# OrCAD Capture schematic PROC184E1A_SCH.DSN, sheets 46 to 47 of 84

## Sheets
46 52. ON BOARD LIN: size C; title: LIN INTERFACE; note: PROC184_SCH
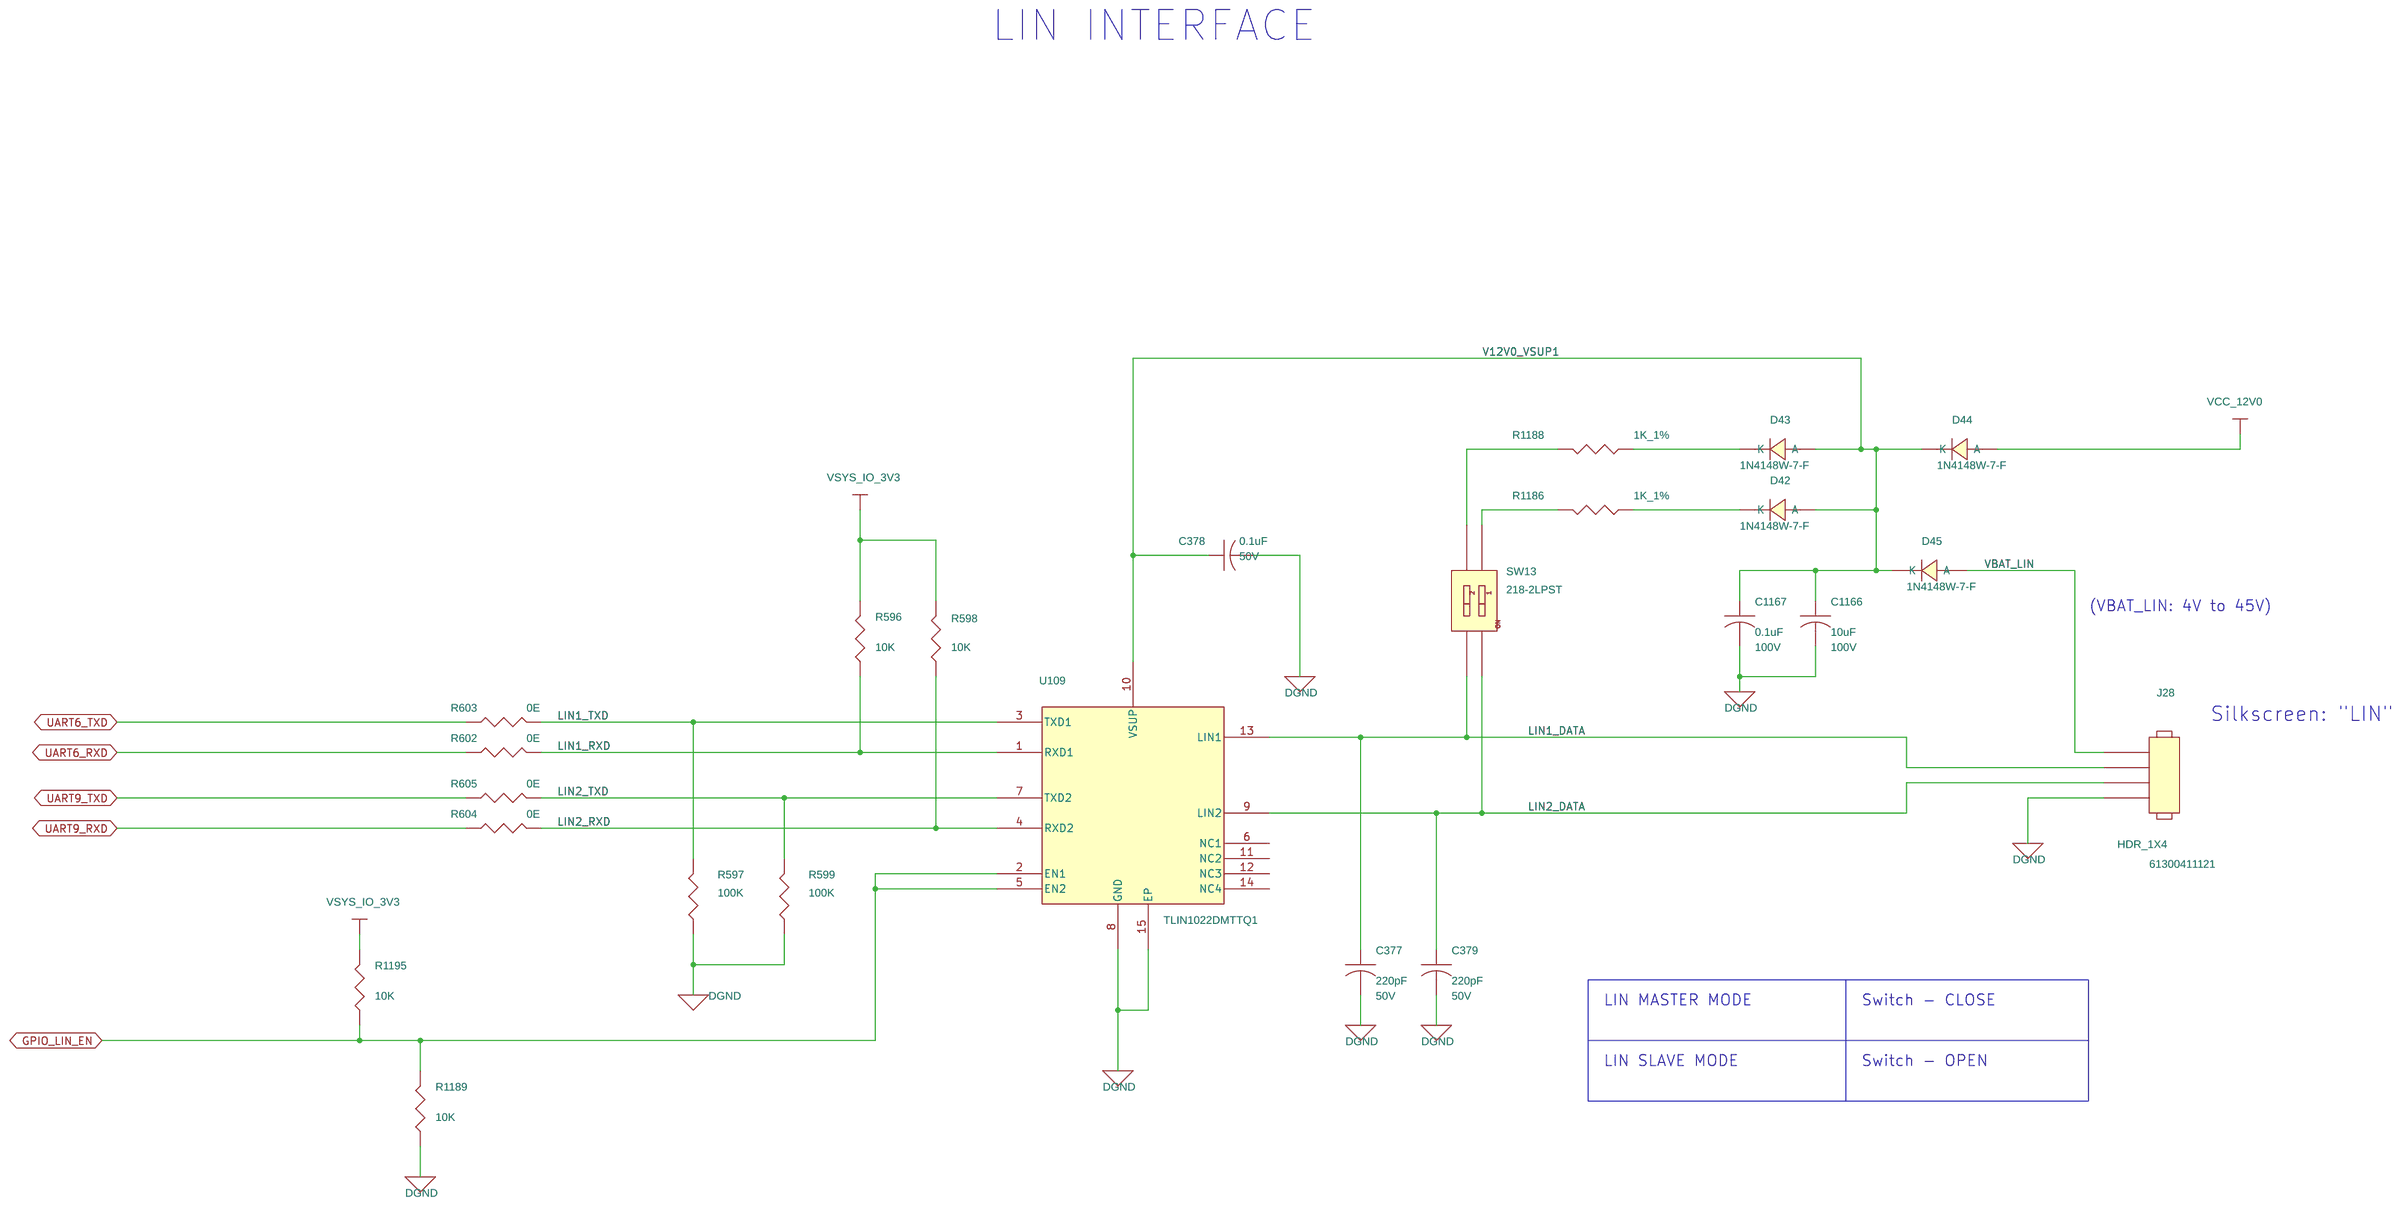
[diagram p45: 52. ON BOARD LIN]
47 50. XDS110 DEBUGGER: size C; title: XDS110 DEBUGGER; note: PROC184_SCH
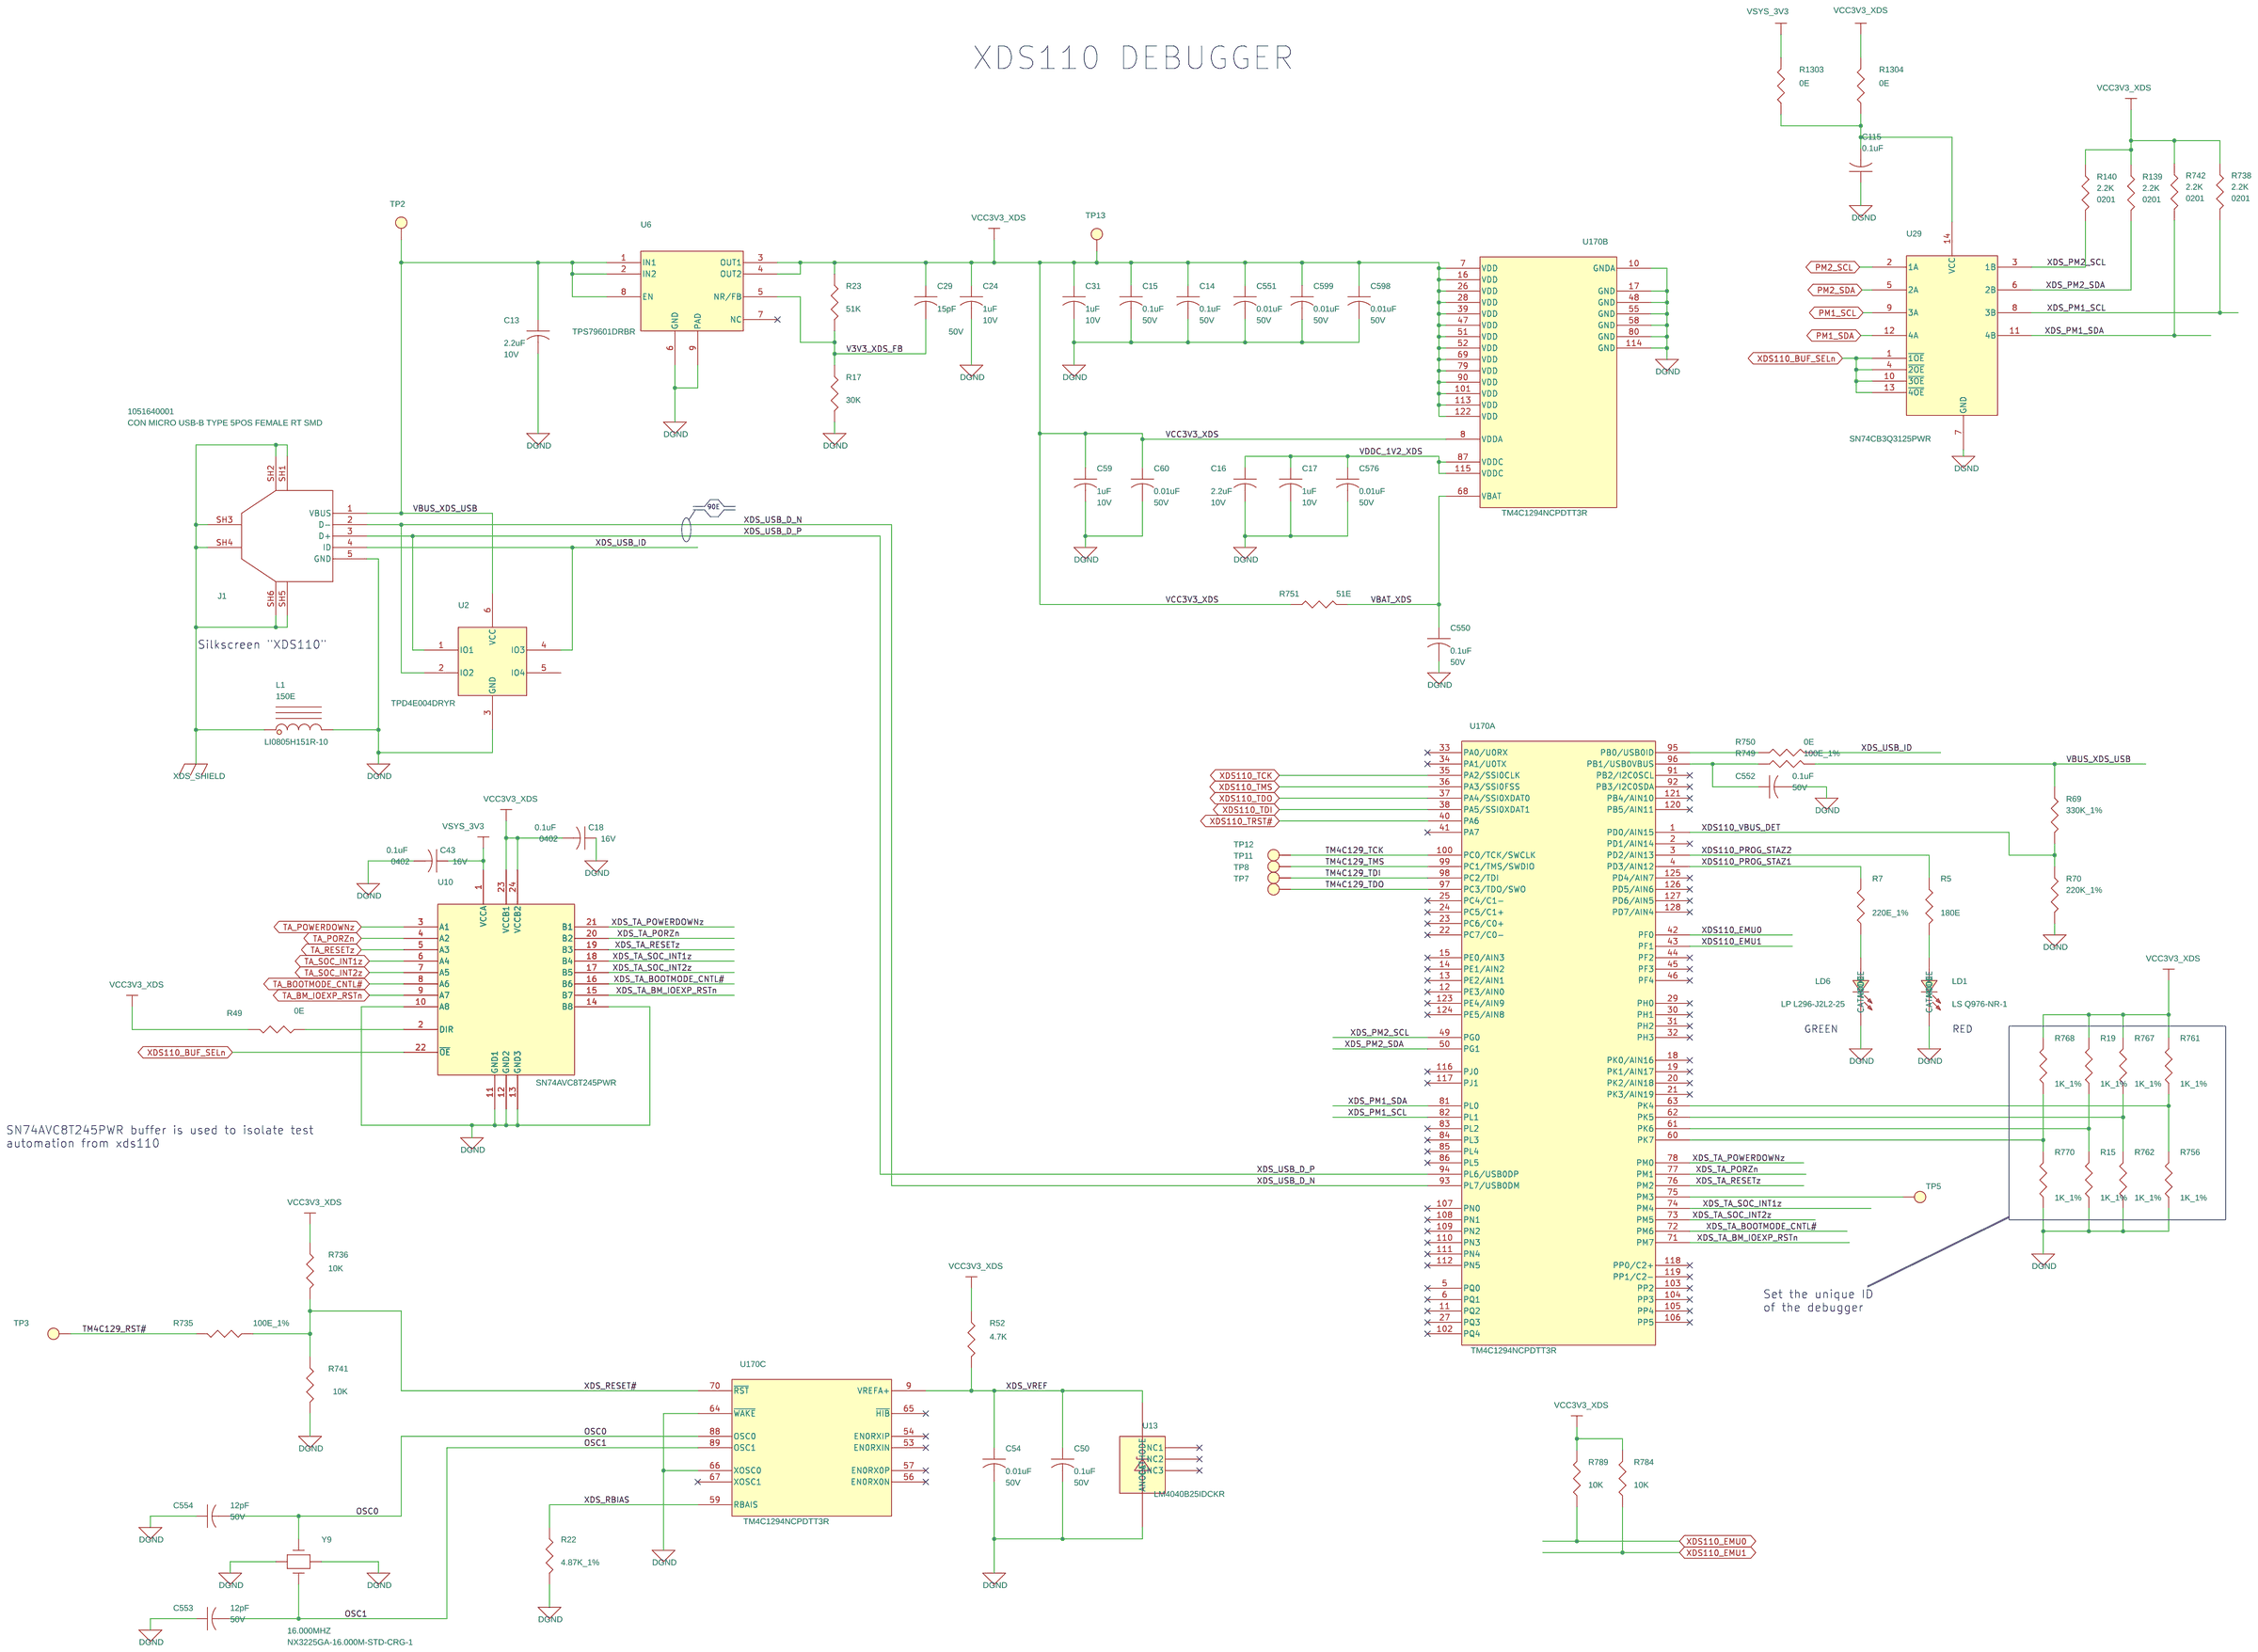
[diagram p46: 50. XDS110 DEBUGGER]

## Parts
sheet 50. XDS110 DEBUGGER
C13  2.2uF  [CAP0402_0-75]
C14  0.1uF  [CAP0402_0-75]
C15  0.1uF  [CAP0402_0-75]
C16  2.2uF  [CAP0402_0-75]
C17  1uF  [CAP0402_0-75]
C18  0.1uF  [CAP0402_0-75]
C24  1uF  [CAP0402_0-75]
C29  15pF  [CAP0402_0-75]
C31  1uF  [CAP0402_0-75]
C43  0.1uF  [CAP0402_0-75]
C50  0.1uF  [CAP0402_0-75]
C54  0.01uF  [CAP0402_0-75]
C59  1uF  [CAP0402_0-75]
C60  0.01uF  [CAP0402_0-75]
C115  0.1uF  [CAP0402_0-75]
C550  0.1uF  [CAP0402_0-75]
C551  0.01uF  [CAP0402_0-75]
C552  0.1uF  [CAP0402_0-75]
C553  12pF  [CAP0402_0-75]
C554  12pF  [CAP0402_0-75]
C576  0.01uF  [CAP0402_0-75]
C598  0.01uF  [CAP0402_0-75]
C599  0.01uF  [CAP0402_0-75]
J1  CON_MUSB-B_5_F  [CON_MUSBB5_1051640001_S_R_S_2-5]
L1  150E  [IND0805_M]
LD1  LS Q976-NR-1  [LED_0603_0-8]
LD6  LP L296-J2L2-25  [LED_0603_0-7]
R5  180E  [RES0402_0-5]
R7  220E_1%  [RES0402_0-5]
R15  1K_1%  [RES0402_0-5]
R17  30K  [RES0402_0-5]
R19  1K_1%  [RES0402_0-5]
R22  4.87K_1%  [RES0402_0-5]
R23  51K  [RES0402_0-5]
R49  0E  [RES0402_0-5]
R52  4.7K  [RES0402_0-5]
R69  330K_1%  [RES0402_0-5]
R70  220K_1%  [RES0402_0-5]
R139  2.2K  [RES0201_0-5]
R140  2.2K  [RES0201_0-5]
R735  100E_1%  [RES0402_0-5]
R736  10K  [RES0402_0-5]
R738  2.2K  [RES0201_0-5]
R741  10K  [RES0402_0-5]
R742  2.2K  [RES0201_0-5]
R749  100E_1%  [RES0402_0-5]
R750  0E  [RES0402_0-5]
R751  51E  [RES0402_0-5]
R756  1K_1%  [RES0402_0-5]
R761  1K_1%  [RES0402_0-5]
R762  1K_1%  [RES0402_0-5]
R767  1K_1%  [RES0402_0-5]
R768  1K_1%  [RES0402_0-5]
R770  1K_1%  [RES0402_0-5]
R784  10K  [RES0402_0-5]
R789  10K  [RES0402_0-5]
R1303  0E  [RES0402_0-5]
R1304  0E  [RES0402_0-5]
TP2  TP30_SMD  [TP30_SMD]
TP3  TP30_SMD  [TP30_SMD]
TP5  TP30_SMD  [TP30_SMD]
TP7  TP30_SMD  [TP30_SMD]
TP8  TP30_SMD  [TP30_SMD]
TP11  TP30_SMD  [TP30_SMD]
TP12  TP30_SMD  [TP30_SMD]
TP13  TP30_SMD  [TP30_SMD]
U2  TPD4E004DRYR  [SON6_19-68_40X60_PB_0-6]
U6  TPS79601DRBR  [SON8_25-59_130X130_1]
U10  SN74AVC8T245PWR  [TSSOP24_25-59_315X180_1-2]
U13  LM4040B25IDCKR  [SC70-5_1-1]
U29  SN74CB3Q3125PWR  [TSSOP14_25-59_205X180_1-2]
U170  TM4C1294NCPDTT3R  [TQFP128_15-74_550X550_1-2]  (sections A,B,C)
Y9  16.000MHZ  [XTAL4_NX3225GA_130X100_SMD_0-9]
sheet 52. ON BOARD LIN
C377  220pF  [CAP0402_0-75]
C378  0.1uF  [CAP0402_0-75]
C379  220pF  [CAP0402_0-75]
C1166  10uF  [CAP1210_2-75]
C1167  0.1uF  [CAP0603_1]
D42  1N4148W-7-F  [DIO_SOD123_1-4]
D43  1N4148W-7-F  [DIO_SOD123_1-4]
D44  1N4148W-7-F  [DIO_SOD123_1-4]
D45  1N4148W-7-F  [DIO_SOD123_1-4]
J28  HDR_1X4  [HDR_1X4_61300411121_S_T_8-6]
R596  10K  [RES0402_0-5]
R597  100K  [RES0402_0-5]
R598  10K  [RES0402_0-5]
R599  100K  [RES0402_0-5]
R602  0E  [RES0402_0-5]
R603  0E  [RES0402_0-5]
R604  0E  [RES0402_0-5]
R605  0E  [RES0402_0-5]
R1186  1K_1%  [RES0402_0-5]
R1188  1K_1%  [RES0402_0-5]
R1189  10K  [RES0402_0-5]
R1195  10K  [RES0402_0-5]
SW13  218-2LPST  [SW4_49-99_150X230_SMD_2-7]
U109  TLIN1022DMTTQ1  [VSON14_25-59_120X180_0-9]

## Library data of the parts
C13 C16 = CAP: CAP CERAMIC 2.2uF 10V 10% X5R 0402; Automotive Alternate_mfr_name: TAIYO YUDEN; Automotive Alternate_mfr_part_number: LMK105ABJ225MVHF; Chkd/date: MANIRAJA/251120; Crtd /date: ALVY/241120; Custom_Duty: 15%; Customs_HS_Code: 85322990; Direct Alternate_mfr_name: TDK; Direct Alternate_mfr_part_number: C1005X5R1A225K050BC; Distributor_name: MOUSER; Distributor_part_number: 81-GRM155R61A225K01D; Footprint Path: Y:\MIS_DATABASE\Library\ALTIUM_TOOL\PCB_FOOTPRINTS\Altium_Footprint_Lib.PcbLib; Height: 0.55MM; Library Path: Y:\MIS_DATABASE\Library\ALTIUM_TOOL\SCHEMATICS_PARTS\MS_DISCRETE_Library.schlib; Manufacturer: MURATA; Mfr_name: MURATA; Mfr_part_number: GRM155R61A225KE01D; Mistral Part No: 120011100038-R; Package: 0402; Part_type: CAPACITORS\CERAMIC; Project: PLCC_DIGITAL BRD PROTO; RoHS: RoHS; Temperature: -55°C+85°C; Tolerance: 10%; Voltage: 10V; Wattage: NA; Weight: 1.6mg; Datasheet: Y:\MIS_DATABASE\DATASHEETS\CAPACITORS\MURATA-GXX-SER_NOV17.PDF
C14 C15 C50 C550 C552 = CAP: CAP CERAMIC 0.1uF 50V 10% X7R 0402; Automotive Alternate_mfr_name: TDK; Automotive Alternate_mfr_part_number: CGA2B3X7R1H104K050BB; Chkd/date: MANIRAJA/261020; Crtd /date: ALVY/211020; Custom_Duty: 15%; Customs_HS_Code: 85322990; Direct Alternate_mfr_name: TDK; Direct Alternate_mfr_part_number: C1005X7R1H104K050BE; Distributor_name: DIGIKEY; Distributor_part_number: 490-10700-1-ND; Footprint Path: Y:\MIS_DATABASE\Library\ALTIUM_TOOL\PCB_FOOTPRINTS\Altium_Footprint_Lib.PcbLib; Height: 0.55MM; Library Path: Y:\MIS_DATABASE\Library\ALTIUM_TOOL\SCHEMATICS_PARTS\MS_DISCRETE_Library.schlib; Manufacturer: MURATA; Mfr_name: MURATA; Mfr_part_number: GRM155R71H104KE14D; Mistral Part No: 120011100014-R; Package: 0402; Part_type: CAPACITORS\CERAMIC; Project: J7_CP; RoHS: RoHS; Temperature: -55°C+125°C; Tolerance: 10%; Voltage: 50V; Wattage: NA; Weight: 3.1mg; Datasheet: Y:\MIS_DATABASE\DATASHEETS\CAPACITORS\GRM155R71H104KE14.PDF
C17 C24 C31 C59 = CAP: CAP CERAMIC 1uF 10V 10% X7S AUTO 0402; Automotive Alternate_mfr_name: TAIYO YUDEN; Automotive Alternate_mfr_part_number: EMK105BJ105KVHF; Chkd/date: MANIRAJA/100918; Crtd /date: ALVY/100918; Custom_Duty: 15%; Customs_HS_Code: 85322990; Direct Alternate_mfr_name: YAGEO AMERICA; Direct Alternate_mfr_part_number: CC0402KRX5R7BB105; Distributor_name: DIGIKEY; Distributor_part_number: 490-13409-1-ND; Footprint Path: Y:\MIS_DATABASE\Library\ALTIUM_TOOL\PCB_FOOTPRINTS\Altium_Footprint_Lib.PcbLib; Height: 0.70MM; Library Path: Y:\MIS_DATABASE\Library\ALTIUM_TOOL\SCHEMATICS_PARTS\MS_DISCRETE_Library.schlib; Manufacturer: TDK CORPORATION; Mfr_name: MURATA; Mfr_part_number: GCM155C71A105KE38D; Mistral Part No: 120018090021-R; Package: 0402; Part_type: CAPACITORS\CERAMIC; Project: SMART-M_SCRIPTALK_PB; RoHS: RoHS; Temperature: -55°C+125°C; Tolerance: 10%; Voltage: 10V; Wattage: NA; Weight: 6mg; Datasheet: Y:\MIS_DATABASE\DATASHEETS\CAPACITORS\MURATA-GCM-SER.PDF
C18 C43 C115 = CAP: CAP CERAMIC 0.1uF 16V 10% X7R AUTO 0402; Automotive Alternate_mfr_name: TDK; Automotive Alternate_mfr_part_number: CGA2B1X7R1C104K050BC; Chkd/date: NAVEED/021014; Crtd /date: VASANTHA/300514; Custom_Duty: 15%; Customs_HS_Code: 85322990; Direct Alternate_mfr_name: MURATA; Direct Alternate_mfr_part_number: GCM155R71C104JA55D; Distributor_name: DIGIKEY; Distributor_part_number: 490-4759-1-ND; Footprint Path: Y:\MIS_DATABASE\Library\ALTIUM_TOOL\PCB_FOOTPRINTS\Altium_Footprint_Lib.PcbLib; Height: 0.55MM; Library Path: Y:\MIS_DATABASE\Library\ALTIUM_TOOL\SCHEMATICS_PARTS\MS_DISCRETE_Library.schlib; Manufacturer: MURATA; Mfr_name: MURATA; Mfr_part_number: GCM155R71C104KA55D; Mistral Part No: 120016070006-R; Package: 0402; Part_type: CAPACITORS\CERAMIC; Project: DCMIST_FPGA_CARD; RoHS: RoHS; Temperature: -55°C+125°C; Tolerance: 10%; Voltage: 16V; Wattage: NA; Weight: 6mg; Datasheet: Y:\MIS_DATABASE\DATASHEETS\CAPACITORS\MURATA-GCM-SER.PDF
C29 = CAP: CAP CERAMIC 15pF 50V 5% C0G(NP0) 0402; Automotive Alternate_mfr_name: TDK; Automotive Alternate_mfr_part_number: CGA2B2C0G1H150J050BA; Chkd/date: MANIRAJA/020419; Crtd /date: MANIRAJA/020419; Custom_Duty: 15%; Customs_HS_Code: 85322990; Direct Alternate_mfr_name: TDK; Direct Alternate_mfr_part_number: C1005NP01H150J050BA; Distributor_name: DIGIKEY; Distributor_part_number: 399-1014-1-ND; Footprint Path: Y:\MIS_DATABASE\Library\ALTIUM_TOOL\PCB_FOOTPRINTS\Altium_Footprint_Lib.PcbLib; Height: 0.55MM; Library Path: Y:\MIS_DATABASE\Library\ALTIUM_TOOL\SCHEMATICS_PARTS\MS_DISCRETE_Library.schlib; Manufacturer: KEMET; Mfr_name: KEMET; Mfr_part_number: C0402C150J5GACTU; Mistral Part No: 120009030233-R; Package: 0402; Part_type: CAPACITORS\CERAMIC; Project: VOCERA; RoHS: RoHS; Temperature: -55°C+125°C; Tolerance: 5%; Voltage: 50V; Wattage: NA; Weight: 0.65mg; Datasheet: Y:\MIS_DATABASE\DATASHEETS\CAPACITORS\KEMET-C0G_SERIES.PDF
C54 C60 C551 C576 C598 C599 = CAP: CAP CERAMIC 0.01uF 50V 10% X7R 0402; Automotive Alternate_mfr_name: TDK; Automotive Alternate_mfr_part_number: CGA2B2X7R1E103K050BA; Chkd/date: MANIRAJA/280319; Crtd /date: MANIRAJA/280319; Custom_Duty: 15%; Customs_HS_Code: 85322990; Direct Alternate_mfr_name: YAGEO AMERICA; Direct Alternate_mfr_part_number: CC0402KRX7R8BB103; Distributor_name: DIGIKEY; Distributor_part_number: 490-4516-1-ND; Footprint Path: Y:\MIS_DATABASE\Library\ALTIUM_TOOL\PCB_FOOTPRINTS\Altium_Footprint_Lib.PcbLib; Height: 0.55MM; Library Path: Y:\MIS_DATABASE\Library\ALTIUM_TOOL\SCHEMATICS_PARTS\MS_DISCRETE_Library.schlib; Manufacturer: MURATA; Mfr_name: MURATA; Mfr_part_number: GRM155R71H103KA88D; Mistral Part No: 120009030025-R; Package: 0402; Part_type: CAPACITORS\CERAMIC; Project: G4_SVGA; RoHS: RoHS; Temperature: -55°C+125°C; Tolerance: 10%; Voltage: 50V; Wattage: NA; Weight: 0.65mg; Datasheet: Y:\MIS_DATABASE\DATASHEETS\CAPACITORS\GRM155R71H103KA88D.PDF
C553 C554 = CAP: CAP CERAMIC 12pF 50V 5% C0G(NP0) 0402; Automotive Alternate_mfr_name: TDK; Automotive Alternate_mfr_part_number: CGA2B2C0G1H120J050BA; Chkd/date: SHREESHAIL/281105; Crtd /date: MAZHAR/040505; Custom_Duty: 15%; Customs_HS_Code: 85322990; Direct Alternate_mfr_name: SAMSUNG; Direct Alternate_mfr_part_number: CL05C120JB5NNNC; Distributor_name: DIGIKEY; Distributor_part_number: 478-1071-1-ND; Footprint Path: Y:\MIS_DATABASE\Library\ALTIUM_TOOL\PCB_FOOTPRINTS\Altium_Footprint_Lib.PcbLib; Height: 0.56MM; Library Path: Y:\MIS_DATABASE\Library\ALTIUM_TOOL\SCHEMATICS_PARTS\MS_DISCRETE_Library.schlib; Manufacturer: AVX CORPORATION; Mfr_name: AVX CORPORATION; Mfr_part_number: 04025A120JAT2A; Mistral Part No: 120015110024-R; Package: 0402; Part_type: CAPACITORS\CERAMIC; Project: EPDA_CORE; RoHS: RoHS; Temperature: -55°C+125°C; Tolerance: 5%; Voltage: 50V; Wattage: NA; Weight: 0.65mg; Datasheet: Y:\MIS_DATABASE\DATASHEETS\CAPACITORS\AVX_MLC.PDF
J1 = CON_MUSB-B_5_1051640001: CON MICRO USB-B TYPE 5POS FEMALE RT SMD; Chkd/date: MANIRAJA/230817; Crtd /date: MANIRAJA/230817; Custom_Duty: 24%; Customs_HS_Code: 85369090; Distributor_name: DIGIKEY; Distributor_part_number: WM11263CT-ND; Height: 2.45MM; Manufacturer: MOLEX; Mfr_name: MOLEX; Mfr_part_number: 1051640001; Mistral Part No: 150017080018-R; Package: SMD; Part_type: CONNECTOR\USB; Project: TI_MAXIE_CPB; RoHS: RoHS; Temperature: -35°C+85°C; Tolerance: NA; Voltage: NA; Wattage: NA; Weight: 234mg; Datasheet: Y:\MIS_DATABASE\DATASHEETS\CONNECTORS\1051640001.PDF
L1 = INDUCTOR_FERRITE: IND FERRITE BEAD 150E 800mA 0805; Automotive Alternate_mfr_name: TDK; Automotive Alternate_mfr_part_number: MMZ2012Y121BTD25; Chkd/date: BALACHANDAR/160514; Crtd /date: SARANYA/080514; Custom_Duty: 24%; Customs_HS_Code: 85437099; Direct Alternate_mfr_name: TDK; Direct Alternate_mfr_part_number: MMZ2012Y121BT000; Distributor_name: DIGIKEY; Distributor_part_number: 240-2384-1-ND; Height: 1.25MM; Manufacturer: LAIRD TECH; Mfr_name: LAIRD TECH; Mfr_part_number: LI0805H151R-10; Mistral Part No: 130014050062-R; Package: 0805; Part_type: INDUCTOR; Project: AEGIS GP BETA2; RoHS: RoHS; Temperature: NA; Tolerance: NA; Voltage: NA; Wattage: NA; Weight: NA; Datasheet: Y:\MIS_DATABASE\DATASHEETS\DISCRETES\INDUCTORS\LIXXX_SERIES.PDF
LD1 = DIODE_LED: LED SUPER RED 0603; Chkd/date: MANIRAJA/150218; Crtd /date: ALVY/150218; Custom_Duty: 24%; Customs_HS_Code: 85437099; Distributor_name: DIGIKEY; Distributor_part_number: 475-2512-1-ND; Footprint Path: Y:\MIS_DATABASE\Library\ALTIUM_TOOL\PCB_FOOTPRINTS\Altium_Footprint_Lib.PcbLib; Height: 0.80MM; Library Path: Y:\MIS_DATABASE\Library\ALTIUM_TOOL\SCHEMATICS_PARTS\MS_OPTO_Library.schlib; Manufacturer: OSRAM; Mfr_name: OSRAM; Mistral Part No: 130018020039-R; Package: 0603; Part_type: OPTO\LED; Project: TI_MAXIE_CPB; RoHS: RoHS; Temperature: -30°C+85°C; Tolerance: NA; Voltage: NA; Wattage: NA; Weight: 1.4mg; Datasheet: Y:\MIS_DATABASE\DATASHEETS\DISCRETES\LEDS\LSQ976-NR-1.PDF
LD6 = DIODE_LED: LED PURE GREEN 0603; Chkd/date: MANIRAJA/230817; Crtd /date: MANIRAJA/230817; Custom_Duty: 24%; Customs_HS_Code: 85437099; Distributor_name: DIGIKEY; Distributor_part_number: 475-2920-1-ND; Footprint Path: Y:\MIS_DATABASE\Library\ALTIUM_TOOL\PCB_FOOTPRINTS\Altium_Footprint_Lib.PcbLib; Height: 0.67MM; Manufacturer: OSRAM; Mfr_name: OSRAM; Mfr_part_number: LP L296-J2L2-25-Z; Mistral Part No: 130017080025-R; Package: 0603; Part_type: OPTO\LED; Project: TI_MAXIE_CPB; RoHS: RoHS; Temperature: -40°C+100°C; Tolerance: NA; Voltage: NA; Wattage: NA; Weight: 2mg; Datasheet: Y:\MIS_DATABASE\DATASHEETS\DISCRETES\LEDS\LPL296-J2L2-25.PDF
R5 = RESISTOR: RES 180E 1/10W 5% 0402; Chkd/date: MAZHAR/150709; Crtd /date: GEETHA/280406; Custom_Duty: 15%; Customs_HS_Code: 85332119; Distributor_name: DIGIKEY; Distributor_part_number: P180JCT-ND; Footprint Path: Y:\MIS_DATABASE\Library\ALTIUM_TOOL\PCB_FOOTPRINTS\Altium_Footprint_Lib.PcbLib; Height: 0.40MM; Library Path: Y:\MIS_DATABASE\Library\ALTIUM_TOOL\SCHEMATICS_PARTS\MS_DISCRETE_Library.schlib; Manufacturer: PANASONIC-ECG; Mfr_name: PANASONIC-ECG; Mfr_part_number: ERJ-2GEJ181X; Mistral Part No: 110009030371-R; Package: 0402; Part_type: RESISTORS\FIXED; Project: RED EYE; RoHS: RoHS; Temperature: -55°C+155°C; Tolerance: 5%; Voltage: NA; Wattage: 1/10W; Weight: 0.8mg; Datasheet: Y:\MIS_DATABASE\DATASHEETS\RESISTORS\PAN-ERJSER_NOV17.PDF
R7 = RESISTOR: RES 220E 1/16W 1% 0402; Chkd/date: MANIRAJA/130917; Crtd /date: MANIRAJA/130917; Custom_Duty: 15%; Customs_HS_Code: 85332119; Distributor_name: DIGIKEY; Distributor_part_number: 311-220LRCT-ND; Footprint Path: Y:\MIS_DATABASE\Library\ALTIUM_TOOL\PCB_FOOTPRINTS\Altium_Footprint_Lib.PcbLib; Height: 0.40MM; Library Path: Y:\MIS_DATABASE\Library\ALTIUM_TOOL\SCHEMATICS_PARTS\MS_DISCRETE_Library.schlib; Manufacturer: YAGEO AMERICA; Mfr_name: YAGEO AMERICA; Mfr_part_number: RC0402FR-07220RL; Mistral Part No: 110019040169-R; Package: 0402; Part_type: RESISTORS\FIXED; Project: TI_SVB_MAXWELL_DUT; RoHS: RoHS; Temperature: -55°C+155°C; Tolerance: 1%; Voltage: NA; Wattage: 1/16W; Weight: 0.65mg; Datasheet: Y:\MIS_DATABASE\DATASHEETS\RESISTORS\RCXXXXL-SER_MAR18.PDF
R15 R756 R762 R770 = RESISTOR: RES 1K 1/10W 1% 0402; Assembly_Instruction: DNI; Chkd/date: VASANTHA/281216; Crtd /date: MAZHAR/150506; Custom_Duty: 15%; Customs_HS_Code: 85332119; Distributor_name: DIGIKEY; Distributor_part_number: P1.00KLCT-ND; Footprint Path: Y:\MIS_DATABASE\Library\ALTIUM_TOOL\PCB_FOOTPRINTS\Altium_Footprint_Lib.PcbLib; Height: 0.40MM; Library Path: Y:\MIS_DATABASE\Library\ALTIUM_TOOL\SCHEMATICS_PARTS\MS_DISCRETE_Library.schlib; Manufacturer: PANASONIC-ECG; Mfr_name: PANASONIC-ECG; Mfr_part_number: ERJ-2RKF1001X; Mistral Part No: 110009030411-R; Package: 0402; Part_type: RESISTORS\FIXED; Project: VOCERA; RoHS: RoHS; Temperature: -55°C+155°C; Tolerance: 1%; Voltage: NA; Wattage: 1/10W; Weight: 0.8mg; Datasheet: Y:\MIS_DATABASE\DATASHEETS\RESISTORS\PAN-ERJSER_NOV17.PDF
R17 = RESISTOR: RES 30K 1/16W 5% 0402; Chkd/date: MANIRAJA/230817; Crtd /date: MANIRAJA/230817; Custom_Duty: 15%; Customs_HS_Code: 85332119; Distributor_name: DIGIKEY; Distributor_part_number: 541-30KJCT-ND; Footprint Path: Y:\MIS_DATABASE\Library\ALTIUM_TOOL\PCB_FOOTPRINTS\Altium_Footprint_Lib.PcbLib; Height: 0.40MM; Library Path: Y:\MIS_DATABASE\Library\ALTIUM_TOOL\SCHEMATICS_PARTS\MS_DISCRETE_Library.schlib; Manufacturer: VISHAY; Mfr_name: VISHAY; Mfr_part_number: CRCW040230K0JNED; Mistral Part No: 110017080023-R; Package: 0402; Part_type: RESISTORS\FIXED; Project: TI_MAXIE_CPB; RoHS: RoHS; Temperature: -55°C+155°C; Tolerance: 5%; Voltage: NA; Wattage: 1/16W; Weight: 0.65mg; Datasheet: Y:\MIS_DATABASE\DATASHEETS\RESISTORS\CRCW0603.PDF
R19 R761 R767 R768 R1186 R1188 = RESISTOR: RES 1K 1/10W 1% 0402; Chkd/date: VASANTHA/281216; Crtd /date: MAZHAR/150506; Custom_Duty: 15%; Customs_HS_Code: 85332119; Distributor_name: DIGIKEY; Distributor_part_number: P1.00KLCT-ND; Footprint Path: Y:\MIS_DATABASE\Library\ALTIUM_TOOL\PCB_FOOTPRINTS\Altium_Footprint_Lib.PcbLib; Height: 0.40MM; Library Path: Y:\MIS_DATABASE\Library\ALTIUM_TOOL\SCHEMATICS_PARTS\MS_DISCRETE_Library.schlib; Manufacturer: PANASONIC-ECG; Mfr_name: PANASONIC-ECG; Mfr_part_number: ERJ-2RKF1001X; Mistral Part No: 110009030411-R; Package: 0402; Part_type: RESISTORS\FIXED; Project: VOCERA; RoHS: RoHS; Temperature: -55°C+155°C; Tolerance: 1%; Voltage: NA; Wattage: 1/10W; Weight: 0.8mg; Datasheet: Y:\MIS_DATABASE\DATASHEETS\RESISTORS\PAN-ERJSER_NOV17.PDF
R22 = RESISTOR: RES 4.87K 1/10W 1% 0402; Chkd/date: MAZHAR/150709; Crtd /date: USMAN/150109; Custom_Duty: 15%; Customs_HS_Code: 85332119; Distributor_name: DIGIKEY; Distributor_part_number: P4.87KLCT-ND; Footprint Path: Y:\MIS_DATABASE\Library\ALTIUM_TOOL\PCB_FOOTPRINTS\Altium_Footprint_Lib.PcbLib; Height: 0.40MM; Library Path: Y:\MIS_DATABASE\Library\ALTIUM_TOOL\SCHEMATICS_PARTS\MS_DISCRETE_Library.schlib; Manufacturer: PANASONIC-ECG; Mfr_name: PANASONIC-ECG; Mfr_part_number: ERJ-2RKF4871X; Mistral Part No: 110009030803-R; Package: 0402; Part_type: RESISTORS\FIXED; Project: BSN-II; RoHS: RoHS; Temperature: -55°C+155°C; Tolerance: 1%; Voltage: NA; Wattage: 1/10W; Weight: 0.8mg; Datasheet: Y:\MIS_DATABASE\DATASHEETS\RESISTORS\PAN-ERJSER_NOV17.PDF
R23 = RESISTOR: RES 51K 1/16W 5% 0402; Chkd/date: MANIRAJA/230817; Crtd /date: MANIRAJA/230817; Custom_Duty: 15%; Customs_HS_Code: 85332119; Distributor_name: DIGIKEY; Distributor_part_number: 541-51KJCT-ND; Footprint Path: Y:\MIS_DATABASE\Library\ALTIUM_TOOL\PCB_FOOTPRINTS\Altium_Footprint_Lib.PcbLib; Height: 0.40MM; Library Path: Y:\MIS_DATABASE\Library\ALTIUM_TOOL\SCHEMATICS_PARTS\MS_DISCRETE_Library.schlib; Manufacturer: VISHAY; Mfr_name: VISHAY; Mfr_part_number: CRCW040251K0JNED; Mistral Part No: 110009030966-R; Package: 0402; Part_type: RESISTORS\FIXED; Project: TI_MAXIE_CPB; RoHS: RoHS; Temperature: -55°C+155°C; Tolerance: 5%; Voltage: NA; Wattage: 1/16W; Weight: 0.65mg; Datasheet: Y:\MIS_DATABASE\DATASHEETS\RESISTORS\CRCW0603.PDF
R49 R602-R605 = RESISTOR: RES 0E 1/10W JUMPER 0402; Chkd/date: VASANTHA/061216; Crtd /date: NAVEED/201014; Custom_Duty: 15%; Customs_HS_Code: 85332119; Distributor_name: DIGIKEY; Distributor_part_number: P0.0JCT-ND; Footprint Path: Y:\MIS_DATABASE\Library\ALTIUM_TOOL\PCB_FOOTPRINTS\Altium_Footprint_Lib.PcbLib; Height: 0.40MM; IBISSP_MODLES: VALUE REPEATING 2 TIME; Library Path: Y:\MIS_DATABASE\Library\ALTIUM_TOOL\SCHEMATICS_PARTS\MS_DISCRETE_Library.schlib; Manufacturer: PANASONIC-ECG; Mfr_name: PANASONIC-ECG; Mfr_part_number: ERJ-2GE0R00X; Mistral Part No: 110018030052-R; Package: 0402; Part_type: RESISTORS\FIXED; Project: AEGIS POM; RoHS: RoHS; Temperature: -55°C+155°C; Tolerance: NA; Voltage: NA; Wattage: 1/10W; Weight: 0.8mg; Datasheet: Y:\MIS_DATABASE\DATASHEETS\RESISTORS\PAN-ERJSER_NOV17.PDF
R52 = RESISTOR: RES 4.7K 1/16W 5% 0402; Chkd/date: VASANTHA/130516; Crtd /date: VASANTHA/130516; Custom_Duty: 15%; Customs_HS_Code: 85332119; Distributor_name: DIGIKEY; Distributor_part_number: 311-4.7KJRCT-ND; Footprint Path: Y:\MIS_DATABASE\Library\ALTIUM_TOOL\PCB_FOOTPRINTS\Altium_Footprint_Lib.PcbLib; Height: 0.40MM; Library Path: Y:\MIS_DATABASE\Library\ALTIUM_TOOL\SCHEMATICS_PARTS\MS_DISCRETE_Library.schlib; Manufacturer: YAGEO AMERICA; Mfr_name: YAGEO AMERICA; Mfr_part_number: RC0402JR-074K7L; Mistral Part No: 110011060001-R; Package: 0402; Part_type: RESISTORS\FIXED; Project: TMDXCSK368; RoHS: RoHS; Temperature: -55°C+155°C; Tolerance: 5%; Voltage: NA; Wattage: 1/16W; Weight: 0.65mg; Datasheet: Y:\MIS_DATABASE\DATASHEETS\RESISTORS\RCXXXXL-SER_MAR18.PDF
R69 = RESISTOR: RES 330K 1/16W 1% 0402; Chkd/date: MANIRAJA/230817; Crtd /date: MANIRAJA/230817; Custom_Duty: 15%; Customs_HS_Code: 85332119; Distributor_name: DIGIKEY; Distributor_part_number: 541-330KLCT-ND; Footprint Path: Y:\MIS_DATABASE\Library\ALTIUM_TOOL\PCB_FOOTPRINTS\Altium_Footprint_Lib.PcbLib; Height: 0.40MM; Library Path: Y:\MIS_DATABASE\Library\ALTIUM_TOOL\SCHEMATICS_PARTS\MS_DISCRETE_Library.schlib; Manufacturer: VISHAY; Mfr_name: VISHAY; Mfr_part_number: CRCW0402330KFKED; Mistral Part No: 110017080024-R; Package: 0402; Part_type: RESISTORS\FIXED; Project: TI_MAXIE_CPB; RoHS: RoHS; Temperature: -55°C+155°C; Tolerance: 1%; Voltage: NA; Wattage: 1/16W; Weight: 0.65mg; Datasheet: Y:\MIS_DATABASE\DATASHEETS\RESISTORS\CRCW0603.PDF
R70 = RESISTOR: RES 220K 1/16W 1% 0402; Chkd/date: MANIRAJA/230817; Crtd /date: MANIRAJA/230817; Custom_Duty: 15%; Customs_HS_Code: 85332119; Distributor_name: DIGIKEY; Distributor_part_number: 541-220KLCT-ND; Footprint Path: Y:\MIS_DATABASE\Library\ALTIUM_TOOL\PCB_FOOTPRINTS\Altium_Footprint_Lib.PcbLib; Height: 0.40MM; Library Path: Y:\MIS_DATABASE\Library\ALTIUM_TOOL\SCHEMATICS_PARTS\MS_DISCRETE_Library.schlib; Manufacturer: VISHAY; Mfr_name: VISHAY; Mfr_part_number: CRCW0402220KFKED; Mistral Part No: 110017080025-R; Package: 0402; Part_type: RESISTORS\FIXED; Project: TI_MAXIE_CPB; RoHS: RoHS; Temperature: -55°C+155°C; Tolerance: 1%; Voltage: NA; Wattage: 1/16W; Weight: 0.65mg; Datasheet: Y:\MIS_DATABASE\DATASHEETS\RESISTORS\CRCW0603.PDF
R139 R140 R738 R742 = RESISTOR: RES 2.2K 1/20W 5% 0201; Chkd/date: MANIRAJA/050517; Crtd /date: MANIRAJA/050517; Custom_Duty: 15%; Customs_HS_Code: 85332119; Distributor_name: DIGIKEY; Distributor_part_number: 311-2.2KNCT-ND; Footprint Path: Y:\MIS_DATABASE\Library\ALTIUM_TOOL\PCB_FOOTPRINTS\Altium_Footprint_Lib.PcbLib; Height: 0.26MM; Library Path: Y:\MIS_DATABASE\Library\ALTIUM_TOOL\SCHEMATICS_PARTS\MS_DISCRETE_Library.schlib; Manufacturer: YAGEO AMERICA; Mfr_name: YAGEO AMERICA; Mfr_part_number: RC0201JR-072K2L; Mistral Part No: 110009030427-R; Package: 0201; Part_type: RESISTORS\FIXED; Project: GOLDEN-I LITE; RoHS: RoHS; Temperature: -55°C+125°C; Tolerance: 5%; Voltage: NA; Wattage: 1/20W; Weight: 0.17mg; Datasheet: Y:\MIS_DATABASE\DATASHEETS\RESISTORS\RCXXXXL-SER_MAR18.PDF
R735 R749 = RESISTOR: RES 100E 1/10W 1% 0402; Chkd/date: MANIRAJA/130617; Crtd /date: JEBRAN/040715; Custom_Duty: 15%; Customs_HS_Code: 85332119; Distributor_name: DIGIKEY; Distributor_part_number: P100LCT-ND; Footprint Path: Y:\MIS_DATABASE\Library\ALTIUM_TOOL\PCB_FOOTPRINTS\Altium_Footprint_Lib.PcbLib; Height: 0.40MM; Library Path: Y:\MIS_DATABASE\Library\ALTIUM_TOOL\SCHEMATICS_PARTS\MS_DISCRETE_Library.schlib; Manufacturer: PANASONIC-ECG; Mfr_name: PANASONIC-ECG; Mfr_part_number: ERJ-2RKF1000X; Mistral Part No: 110018020036-R; Package: 0402; Part_type: RESISTORS\FIXED; Project: CYPHY_FVB; RoHS: RoHS; Temperature: -55°C+155°C; Tolerance: 1%; Voltage: NA; Wattage: 1/10W; Weight: 0.8mg; Datasheet: Y:\MIS_DATABASE\DATASHEETS\RESISTORS\PAN-ERJSER_NOV17.PDF
R596 R598 R736 R784 R789 R1189 R1195 = RESISTOR: RES 10K 1/16W 5% 0402; Chkd/date: VASANTHA/061216; Crtd /date: MAZHAR/230805; Custom_Duty: 15%; Customs_HS_Code: 85332119; Distributor_name: DIGIKEY; Distributor_part_number: 311-10KJRCT-ND; Footprint Path: Y:\MIS_DATABASE\Library\ALTIUM_TOOL\PCB_FOOTPRINTS\Altium_Footprint_Lib.PcbLib; Height: 0.40MM; Library Path: Y:\MIS_DATABASE\Library\ALTIUM_TOOL\SCHEMATICS_PARTS\MS_DISCRETE_Library.schlib; Manufacturer: YAGEO AMERICA; Mfr_name: YAGEO AMERICA; Mfr_part_number: RC0402JR-0710KL; Mistral Part No: 110011060021-R; Package: 0402; Part_type: RESISTORS\FIXED; Project: HSE; RoHS: RoHS; Temperature: -55°C+155°C; Tolerance: 5%; Voltage: NA; Wattage: 1/16W; Weight: 0.65mg; Datasheet: Y:\MIS_DATABASE\DATASHEETS\RESISTORS\RCXXXXL-SER_MAR18.PDF
R741 = RESISTOR: RES 10K 1/16W 5% 0402; Assembly_Instruction: DNI; Chkd/date: VASANTHA/061216; Crtd /date: MAZHAR/230805; Custom_Duty: 15%; Customs_HS_Code: 85332119; Distributor_name: DIGIKEY; Distributor_part_number: 311-10KJRCT-ND; Footprint Path: Y:\MIS_DATABASE\Library\ALTIUM_TOOL\PCB_FOOTPRINTS\Altium_Footprint_Lib.PcbLib; Height: 0.40MM; Library Path: Y:\MIS_DATABASE\Library\ALTIUM_TOOL\SCHEMATICS_PARTS\MS_DISCRETE_Library.schlib; Manufacturer: YAGEO AMERICA; Mfr_name: YAGEO AMERICA; Mfr_part_number: RC0402JR-0710KL; Mistral Part No: 110011060021-R; Package: 0402; Part_type: RESISTORS\FIXED; Project: HSE; RoHS: RoHS; Temperature: -55°C+155°C; Tolerance: 5%; Voltage: NA; Wattage: 1/16W; Weight: 0.65mg; Datasheet: Y:\MIS_DATABASE\DATASHEETS\RESISTORS\RCXXXXL-SER_MAR18.PDF
R750 R1303 R1304 = RESISTOR: RES 0E 1/10W JUMPER 0402; Assembly_Instruction: DNI; Chkd/date: VASANTHA/061216; Crtd /date: NAVEED/201014; Custom_Duty: 15%; Customs_HS_Code: 85332119; Distributor_name: DIGIKEY; Distributor_part_number: P0.0JCT-ND; Footprint Path: Y:\MIS_DATABASE\Library\ALTIUM_TOOL\PCB_FOOTPRINTS\Altium_Footprint_Lib.PcbLib; Height: 0.40MM; IBISSP_MODLES: VALUE REPEATING 2 TIME; Library Path: Y:\MIS_DATABASE\Library\ALTIUM_TOOL\SCHEMATICS_PARTS\MS_DISCRETE_Library.schlib; Manufacturer: PANASONIC-ECG; Mfr_name: PANASONIC-ECG; Mfr_part_number: ERJ-2GE0R00X; Mistral Part No: 110018030052-R; Package: 0402; Part_type: RESISTORS\FIXED; Project: AEGIS POM; RoHS: RoHS; Temperature: -55°C+155°C; Tolerance: NA; Voltage: NA; Wattage: 1/10W; Weight: 0.8mg; Datasheet: Y:\MIS_DATABASE\DATASHEETS\RESISTORS\PAN-ERJSER_NOV17.PDF
R751 = RESISTOR: RES 51E 1/10W 5% 0402; Chkd/date: VASANTHA/291216; Crtd /date: MAZHAR/120505; Custom_Duty: 15%; Customs_HS_Code: 85332119; Distributor_name: DIGIKEY; Distributor_part_number: P51JCT-ND; Footprint Path: Y:\MIS_DATABASE\Library\ALTIUM_TOOL\PCB_FOOTPRINTS\Altium_Footprint_Lib.PcbLib; Height: 0.40MM; Library Path: Y:\MIS_DATABASE\Library\ALTIUM_TOOL\SCHEMATICS_PARTS\MS_DISCRETE_Library.schlib; Manufacturer: PANASONIC-ECG; Mfr_name: PANASONIC-ECG; Mfr_part_number: ERJ-2GEJ510X; Mistral Part No: 110009030962-R; Package: 0402; Part_type: RESISTORS\FIXED; Project: CTP02_REVA_BASE; RoHS: RoHS; Temperature: -55°C+155°C; Tolerance: 5%; Voltage: NA; Wattage: 1/10W; Weight: 0.8mg; Datasheet: Y:\MIS_DATABASE\DATASHEETS\RESISTORS\PAN-ERJSER_NOV17.PDF
TP2 TP3 TP5 TP7 TP8 TP11-TP13 = TESTPOINT: TESTPOINT CIR 30 SMD; Chkd/date: SHREESHAIL/171006; Crtd /date: MAZHAR/171006; Custom_Duty: NA; Customs_HS_Code: NA; Distributor_name: NA; Distributor_part_number: NA; Footprint Path: Y:\MIS_DATABASE\Library\ALTIUM_TOOL\PCB_FOOTPRINTS\Altium_Footprint_Lib.PcbLib; Height: NA; Library Path: Y:\MIS_DATABASE\Library\ALTIUM_TOOL\SCHEMATICS_PARTS\MS_DISCRETE_Library.schlib; MECHANICAL 3D STEP FILE: NA; Manufacturer: LOCAL; Mfr_name: LOCAL; Mistral Part No: 130009030930; Package: SMD; Project: BT MODULE_CSRBC04; RoHS: NA; Temperature: NA; Tolerance: NA; Voltage: NA; Wattage: NA; Weight: NA; Datasheet: NA
U2 = TPD4E004_SON6: IC 4-CH ESD PROTECTION ARRAY FOR HIGH SPEED DATA INTERFACE SON6; Chkd/date: MANIRAJA/100320; Crtd /date: MUDDU/010310; Custom_Duty: 15%; Customs_HS_Code: 85423100; Distributor_name: DIGIKEY; Distributor_part_number: 296-23618-1-ND; Footprint Path: Y:\MIS_DATABASE\Library\ALTIUM_TOOL\PCB_FOOTPRINTS\Altium_Footprint_Lib.PcbLib; Height: 0.60MM; Library Path: Y:\MIS_DATABASE\Library\ALTIUM_TOOL\SCHEMATICS_PARTS\MS_MISCINTERFACE_Library.schlib; Manufacturer: TEXAS INSTRUMENTS; Mfr_name: TEXAS INSTRUMENTS; Mistral Part No: 141010020012-R; Package: SON6; Part_type: ICS\INTERFACE; Project: BUG_BASE-II; RoHS: RoHS; Temperature: -40°C+85°C; Tolerance: NA; Voltage: NA; Wattage: NA; Weight: 3.2mg; Datasheet: Y:\MIS_DATABASE\DATASHEETS\ICS\INTERFACE\TPD4E004-SER.PDF
U6 = TPS79601DRBR_SON8: IC 1A HIGH PSRR RF ADJ LDO LINEAR REGULATOR SON8; Chkd/date: MANIRAJA/030518; Crtd /date: MAZHAR/280809; Custom_Duty: 15%; Customs_HS_Code: 85423100; Distributor_name: DIGIKEY; Distributor_part_number: 296-23107-1-ND; Footprint Path: Y:\MIS_DATABASE\Library\ALTIUM_TOOL\PCB_FOOTPRINTS\Altium_Footprint_Lib.PcbLib; Height: 1.00MM; Library Path: Y:\MIS_DATABASE\Library\ALTIUM_TOOL\SCHEMATICS_PARTS\MS_MISCPOWER_Library.schlib; Manufacturer: TEXAS INSTRUMENTS; Mfr_name: TEXAS INSTRUMENTS; Mistral Part No: 142009080012-R; Package: SON8; Part_type: ICS\POWER\VOLTAGE REGULATOR; Project: DIO_TXRX; RoHS: RoHS; Temperature: -40°C+125°C; Tolerance: NA; Voltage: NA; Wattage: NA; Weight: 24mg; Datasheet: Y:\MIS_DATABASE\DATASHEETS\MISC\REGULATORS\TPS796XX.PDF
U10 = SN74AVC8T245PWR_TSSOP24: IC 8-BIT DUAL-SUPPLY BUS TRANSCEIVER TSSOP24; Chkd/date: MANIRAJA/040917; Crtd /date: USMAN/040509; Custom_Duty: 15%; Customs_HS_Code: 85423100; Distributor_name: DIGIKEY; Distributor_part_number: 296-19100-1-ND; Height: 1.20MM; Mfr_name: TEXAS INSTRUMENTS; Mistral Part No: 143009060004-R; Package: TSSOP24; Part_type: ICS\TELECOM\TRANSCEIVER; Project: STORM2; RoHS: RoHS; Temperature: -40°C+85°C; Tolerance: NA; Voltage: NA; Wattage: NA; Weight: 89.5mg; Datasheet: Y:\MIS_DATABASE\DATASHEETS\ICS\DIGITAL\BUSTRANSCEIVER\SN74AVC8T245.PDF
U13 = LM4040B25IDCKR_SC70-5: IC PRECISION MICROPOWER SHUNT VOLTAGE REFERENCE SC70-5; Automotive Alternate_mfr_name: TEXAS INSTRUMENTS; Automotive Alternate_mfr_part_number: TL4050B25QDCKRQ1; Chkd/date: MANIRAJA/230817; Crtd /date: MANIRAJA/230817; Custom_Duty: 15%; Customs_HS_Code: 85423100; Distributor_name: DIGIKEY; Distributor_part_number: 296-20873-1-ND; Height: 1.10MM; Manufacturer: TEXAS INSTRUMENTS; Mfr_name: TEXAS INSTRUMENTS; Mistral Part No: 142017080015-R; Package: SC70-5; Part_type: ICS\POWER\VOLTAGE REGULATOR; Project: TI_MAXIE_CPB; RoHS: RoHS; Temperature: -40°C+85°C; Tolerance: NA; Voltage: NA; Wattage: NA; Weight: 30mg; Datasheet: Y:\MIS_DATABASE\DATASHEETS\ICS\POWER\LM4040B25I.PDF
U29 = SN74CBTLV3125PWR_TSSOP14: IC 2.5/3.3V QUADRUPLE HIGH-BANDWIDTH FET BUS SWITCH TSSOP14; Chkd/date: MANIRAJA/241018; Crtd /date: ALVY/241018; Custom_Duty: 15%; Customs_HS_Code: 85423100; Distributor_name: DIGIKEY; Distributor_part_number: 296-16804-1-ND; Footprint Path: Y:\MIS_DATABASE\Library\ALTIUM_TOOL\PCB_FOOTPRINTS\Altium_Footprint_Lib.PcbLib; Height: 1.20MM; Library Path: Y:\MIS_DATABASE\Library\ALTIUM_TOOL\SCHEMATICS_PARTS\MS_COMBINATIONAL_Library.schlib; Manufacturer: TEXAS INSTRUMENTS; Mfr_name: TEXAS INSTRUMENTS; Mistral Part No: 141018100021-R; Package: TSSOP14; Part_type: ICS\DIGITAL\COMBINATIONAL; Project: TI_J7ES_EVM_CP; RoHS: RoHS; Temperature: -40°C+85°C; Tolerance: NA; Voltage: NA; Wattage: NA; Weight: 57.2mg; Datasheet: Y:\MIS_DATABASE\DATASHEETS\ICS\DIGITAL\COMBINATIONAL\SN74CB3Q3125.PDF
U170 = TM4C1294NCPDTT3R_TQFP128: IC 32-BIT MICROCONTROLLER WITH 1MB FLASH TQFP128; Chkd/date: MANIRAJA/220817; Crtd /date: MANIRAJA/220817; Custom_Duty: 15%; Customs_HS_Code: 85423100; Distributor_name: DIGIKEY; Distributor_part_number: TM4C1294NCPDTT3R-ND; Height: 1.20MM; Manufacturer: TEXAS INSTRUMENTS; Mfr_name: TEXAS INSTRUMENTS; Mistral Part No: 141217080002-R; Package: TQF9128; Part_type: ICS\DIGITAL\MICROCONTROLLER; Project: TI_MAXIE_CPB; RoHS: RoHS; Temperature: -40°C+105°C; Tolerance: NA; Voltage: NA; Wattage: NA; Weight: 503.5mg; Datasheet: Y:\MIS_DATABASE\DATASHEETS\ICS\DIGITAL\MICROCONTROLLER\TM4C1294NCPD.PDF
Y9 = CRY4_13: CRY 16.000MHz SMD; Chkd/date: MANIRAJA/230817; Crtd /date: MANIRAJA/230817; Custom_Duty: 24%; Customs_HS_Code: 85439000; Distributor_name: DIGIKEY; Distributor_part_number: 644-1157-1-ND; Height: 0.90MM; Manufacturer: NDK; Mfr_name: NDK; Mfr_part_number: NX3225GA-16.000M-STD-CRG-1; Mistral Part No: 130017080024-R; Package: SMD; Part_type: CRYSTAL; Project: TI_MAXIE_CPB; RoHS: RoHS; Temperature: -40°C+85°C; Tolerance: NA; Voltage: NA; Wattage: NA; Weight: NA; Datasheet: Y:\MIS_DATABASE\DATASHEETS\MISC\CRY_OSC\NX3225GA.PDF
C377 C379 = CAP: CAP CERAMIC 220pF 50V 2% C0G(NP0) 0402; Chkd/date: MANIRAJA/030619; Crtd /date: ALVY/310519; Custom_Duty: 15%; Customs_HS_Code: 85322990; Distributor_name: DIGIKEY; Distributor_part_number: 311-3739-1-ND; Footprint Path: Y:\MIS_DATABASE\Library\ALTIUM_TOOL\PCB_FOOTPRINTS\Altium_Footprint_Lib.PcbLib; Height: 0.55MM; Library Path: Y:\MIS_DATABASE\Library\ALTIUM_TOOL\SCHEMATICS_PARTS\MS_DISCRETE_Library.schlib; Manufacturer: YAGEO AMERICA; Mfr_name: YAGEO AMERICA; Mfr_part_number: CC0402GRNPO9BN221; Mistral Part No: 120014070004-R; Package: 0402; Part_type: CAPACITORS\CERAMIC; Project: J7ES_SOM_DUAL-LEO_PMIC; RoHS: RoHS; Temperature: -55°C+125°C; Tolerance: 2%; Voltage: 50V; Wattage: NA; Weight: 0.65mg; Datasheet: Y:\MIS_DATABASE\DATASHEETS\CAPACITORS\YACC-NPO.PDF
C378 = CAP: CAP CERAMIC 0.1uF 50V 10% X7R 0402; Chkd/date: MANIRAJA/261020; Crtd /date: ALVY/211020; Custom_Duty: 15%; Customs_HS_Code: 85322990; Distributor_name: DIGIKEY; Distributor_part_number: 490-10700-1-ND; Footprint Path: Y:\MIS_DATABASE\Library\ALTIUM_TOOL\PCB_FOOTPRINTS\Altium_Footprint_Lib.PcbLib; Height: 0.55MM; Library Path: Y:\MIS_DATABASE\Library\ALTIUM_TOOL\SCHEMATICS_PARTS\MS_DISCRETE_Library.schlib; Manufacturer: MURATA; Mfr_name: MURATA; Mfr_part_number: GRM155R71H104KE14D; Mistral Part No: 120011100014-R; Package: 0402; Part_type: CAPACITORS\CERAMIC; Project: J7_CP; RoHS: RoHS; Temperature: -55°C+125°C; Tolerance: 10%; Voltage: 50V; Wattage: NA; Weight: 3.1mg; Datasheet: Y:\MIS_DATABASE\DATASHEETS\CAPACITORS\GRM155R71H104KE14.PDF
C1166 = CAP: CAP CERAMIC 10uF 100V 10% X7S 1210; Chkd/date: MANIRAJA/280819; Crtd /date: MANIRAJA/280819; Custom_Duty: 15%; Customs_HS_Code: 85322990; Distributor_name: DIGIKEY; Distributor_part_number: 490-16266-1-ND; Footprint Path: Y:\MIS_DATABASE\Library\ALTIUM_TOOL\PCB_FOOTPRINTS\Altium_Footprint_Lib.PcbLib; Height: 2.70MM; Library Path: Y:\MIS_DATABASE\Library\ALTIUM_TOOL\SCHEMATICS_PARTS\MS_DISCRETE_Library.schlib; Manufacturer: MURATA; Mfr_name: MURATA; Mfr_part_number: GRM32EC72A106KE05L; Mistral Part No: 120019080009-R; Package: 1210; Part_type: CAPACITORS\CERAMIC; Project: TI_J7ES_GESI_EXP_BOARD; RoHS: RoHS; Temperature: -55°C+125°C; Tolerance: 10%; Voltage: 100V; Wattage: NA; Weight: 110mg; Datasheet: Y:\MIS_DATABASE\DATASHEETS\CAPACITORS\GRM32EC72A106KE05.PDF
C1167 = CAP: CAP CERAMIC 0.1uF 100V 10% X7R 0603; Chkd/date: MANIRAJA/170420; Crtd /date: ALVY/170420; Custom_Duty: 15%; Customs_HS_Code: 85322990; Distributor_name: DIGIKEY; Distributor_part_number: 490-3285-1-ND; Footprint Path: Y:\MIS_DATABASE\Library\ALTIUM_TOOL\PCB_FOOTPRINTS\Altium_Footprint_Lib.PcbLib; Height: 0.90MM; Library Path: Y:\MIS_DATABASE\Library\ALTIUM_TOOL\SCHEMATICS_PARTS\MS_DISCRETE_Library.schlib; Manufacturer: TDK CORPORATION; Mfr_name: MURATA; Mfr_part_number: GRM188R72A104KA35D; Mistral Part No: 120017010012-R; Package: 0603; Part_type: CAPACITORS\CERAMIC; Project: CUSTOM DCA1000; RoHS: RoHS; Temperature: -55°C+125°C; Tolerance: 10%; Voltage: 100V; Wattage: NA; Weight: 6.3mg; Datasheet: Y:\MIS_DATABASE\DATASHEETS\CAPACITORS\GRM188R72A104KA35.PDF
D42-D45 = DIODE: DIODE SWITCH 400mW 100V SOD123; Chkd/date: VASANTHA/220317; Crtd /date: MANIRAJA/150317; Custom_Duty: 15%; Customs_HS_Code: 85412900; Distributor_name: DIGIKEY; Distributor_part_number: 1N4148W-FDICT-ND; Height: 1.35MM; Manufacturer: DIODES INC; Mfr_name: DIODES INC; Mistral Part No: 130009030246-R; Package: SOD123; Part_type: DIODE\SWITCHING; Project: REVA-IBMS; RoHS: RoHS; Temperature: -65°C+150°C; Tolerance: NA; Voltage: 100V; Wattage: 400mW; Weight: 0.01g; Datasheet: Y:\MIS_DATABASE\DATASHEETS\DISCRETES\DIODES\1N4148W.PDF
J28 = HEADER_4X1: CON HDR 1X4 2.54MM PITCH ST TH; Chkd/date: MANIRAJA/210918; Crtd /date: ALVY/210918; Custom_Duty: 24%; Customs_HS_Code: 85369090; Distributor_name: DIGIKEY; Distributor_part_number: 732-5317-ND; Footprint Path: Y:\MIS_DATABASE\Library\ALTIUM_TOOL\PCB_FOOTPRINTS\Altium_Footprint_Lib.PcbLib; Height: 8.54MM; Library Path: Y:\MIS_DATABASE\Library\ALTIUM_TOOL\SCHEMATICS_PARTS\MS_CONNECTOR_Library.schlib; Manufacturer: WURTH ELECTRONICS INC; Mfr_name: WURTH ELECTRONICS INC; Mfr_part_number: 61300411121; Mistral Part No: 150018090038-R; Package: THRU-HOLE; Part_type: CONNECTOR\HEADERS; Project: TI_60GHz-AOP; RoHS: RoHS; Temperature: -40°C+105°C; Tolerance: NA; Voltage: NA; Wattage: NA; Weight: 210mg; Datasheet: Y:\MIS_DATABASE\DATASHEETS\CONNECTORS\6130XXX.PDF
R597 R599 = RESISTOR: RES 100K 1/10W 5% 0402; Chkd/date: VASANTHA/291216; Crtd /date: GEETHA/190406; Custom_Duty: 15%; Customs_HS_Code: 85332119; Distributor_name: DIGIKEY; Distributor_part_number: P100KJCT-ND; Footprint Path: Y:\MIS_DATABASE\Library\ALTIUM_TOOL\PCB_FOOTPRINTS\Altium_Footprint_Lib.PcbLib; Height: 0.40MM; Library Path: Y:\MIS_DATABASE\Library\ALTIUM_TOOL\SCHEMATICS_PARTS\MS_DISCRETE_Library.schlib; Manufacturer: PANASONIC-ECG; Mfr_name: PANASONIC-ECG; Mfr_part_number: ERJ-2GEJ104X; Mistral Part No: 110009030177-R; Package: 0402; Part_type: RESISTORS\FIXED; Project: RED EYE; RoHS: RoHS; Temperature: -55°C+155°C; Tolerance: 5%; Voltage: NA; Wattage: 1/10W; Weight: 0.8mg; Datasheet: Y:\MIS_DATABASE\DATASHEETS\RESISTORS\PAN-ERJSER_NOV17.PDF
SW13 = SW4_GDH02S04: SWITCH DIP SPST HALF PITCH 2POS SMD; Chkd/date: VASANTHA/080715; Crtd /date: VASANTHA/241221; Custom_Duty: 24%; Customs_HS_Code: 85369090; Distributor_name: DIGIKEY; Distributor_part_number: CT2182LPST-ND; Height: 2.65MM; Manufacturer: CTS; Mfr_name: CTS; Mistral Part No: 130014120040-R; Package: SMD; Part_type: ELECTRO-MECHANICAL\SWITCH; Project: FREE SCALE POM; RoHS: RoHS; Temperature: -55°C+85°C; Tolerance: NA; Voltage: NA; Wattage: NA; Weight: NA; Datasheet: Y:\MIS_DATABASE\DATASHEETS\MISC\SWITCHES\128-12LPST.PDF
U109 = TLIN1022DMTTQ1_VSON14: IC DUAL LOCAL INTERCONNECT NETWORK TRANSCEIVER WITH DOMINANT STATE TIMEOUT VSON14; Chkd/date: MANIRAJA/230819; Crtd /date: MANIRAJA/230819; Custom_Duty: 15%; Customs_HS_Code: 85423100; Distributor_name: DIGIKEY; Distributor_part_number: 296-51677-1-ND; Footprint Path: Y:\MIS_DATABASE\Library\ALTIUM_TOOL\PCB_FOOTPRINTS\Altium_Footprint_Lib.PcbLib; Height: 0.90MM; Library Path: Y:\MIS_DATABASE\Library\ALTIUM_TOOL\SCHEMATICS_PARTS\MS_LINEDRIVERRECEIVER_Library.schlib; Manufacturer: TEXAS INSTRUMENTS; Mfr_name: TEXAS INSTRUMENTS; Mistral Part No: 141019080012-R; Package: VSON14; Part_type: ICS\DIGITAL\BUSTRANSCEIVER; Project: TI_J7ES_GESI_EXP_BOARD; RoHS: RoHS; Temperature: -40°C+125°C; Tolerance: NA; Voltage: NA; Wattage: NA; Weight: 37.3mg; Datasheet: Y:\MIS_DATABASE\DATASHEETS\ICS\DIGITAL\BUSTRANSCEIVER\TLIN1022-Q1.PDF

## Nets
DGND: C13.2 C14.2 C15.2 C16.2 C17.2 C18.1 C24.2 C31.2 C43.2 C50.2 C54.2 C59.2 C60.2 C115.1 C377.2 C378.2 C379.2 C550.2 C551.2 C552.2 C553.1 C554.1 C576.2 C598.2 C599.2 C1166.2 C1167.2 J1.5(GND) J28.4 L1.2 LD1.1(CATHODE) LD6.1(CATHODE) R15.1 R17.2 R22.2 R70.2 R597.1 R599.1 R741.2 R756.1 R762.1 R770.1 R1189.1 U2.3(GND) U6.6(GND) U6.9(PAD) U10.10(A8) U10.11(GND1) U10.12(GND2) U10.13(GND3) U10.14(B8) U13.1(ANODE) U29.7(GND) U109.8(GND) U109.15(EP) U170.10(GNDA) U170.17(GND) U170.48(GND) U170.55(GND) U170.58(GND) U170.64(~{WAKE}) U170.66(XOSC0) U170.80(GND) U170.114(GND) Y9.2 Y9.4 ; also on sheet 11 12 13 14 15 16 17 18 20 21 22 23 24 25 26 27 28 29 30 31 32 33 34 35 36 37 38 39 40 41 42 43 44 45 48 49 50 51 52 53 54 55 56 57 58 59 60 61 62 63 64 65 66 67 68 69 70 71 72 73 76 77 78 79 81 82 83 84
V3V3_XDS_FB: C29.2 R17.1 R23.2 U6.5(NR/FB)
V12V0_VSUP1: C378.1 C1166.1 C1167.1 D42.2(A) D43.2(A) D44.1(K) D45.1(K) U109.10(VSUP)
VBAT_LIN: D45.2(A) J28.1
VBAT_XDS: C550.1 R751.2 U170.68(VBAT)
VBUS_XDS_USB: C13.1 J1.1(VBUS) R69.1 R749.2 TP2.1(TP) U2.6(VCC) U6.1(IN1) U6.2(IN2) U6.8(EN)
VCC3V3_XDS: C14.1 C15.1 C18.2 C24.1 C29.1 C31.1 C59.1 C60.1 C551.1 C598.1 C599.1 R19.2 R23.1 R49.2 R52.1 R139.1 R140.1 R736.1 R738.1 R742.1 R751.1 R761.2 R767.2 R768.2 R784.2 R789.2 R1304.2 TP13.1(TP) U6.3(OUT1) U6.4(OUT2) U10.23(VCCB1) U10.24(VCCB2) U170.7(VDD) U170.8(VDDA) U170.16(VDD) U170.26(VDD) U170.28(VDD) U170.39(VDD) U170.47(VDD) U170.51(VDD) U170.52(VDD) U170.69(VDD) U170.79(VDD) U170.90(VDD) U170.101(VDD) U170.113(VDD) U170.122(VDD) ; also on sheet 22
VCC_12V0: D44.2(A) ; also on sheet 30 31 50 53 59 60 64 66 83
VDDC_1V2_XDS: C16.1 C17.1 C576.1 U170.87(VDDC) U170.115(VDDC)
GPIO_LIN_EN: R1189.2 R1195.1 U109.2(EN1) U109.5(EN2) ; also on sheet 30 38
LIN1_DATA: C377.1 J28.2 SW13.3 U109.13(LIN1)
LIN1_RXD: R596.1 R602.2 U109.1(RXD1)
LIN1_TXD: R597.2 R603.2 U109.3(TXD1)
LIN2_DATA: C379.1 J28.3 SW13.4 U109.9(LIN2)
LIN2_RXD: R598.1 R604.2 U109.4(RXD2)
LIN2_TXD: R599.2 R605.2 U109.7(TXD2)
OSC0: C554.2 U170.88(OSC0) Y9.1
OSC1: C553.2 U170.89(OSC1) Y9.3
PM1_SCL: U29.9(3A) ; also on sheet 63 73 76 78
PM1_SDA: U29.12(4A) ; also on sheet 63 73 76 78
PM2_SCL: U29.2(1A) ; also on sheet 62 63 73 77 79
PM2_SDA: U29.5(2A) ; also on sheet 62 63 73 77 79
TA_BM_IOEXP_RSTn: U10.9(A7) ; also on sheet 62 63
TA_BOOTMODE_CNTL#: U10.8(A6) ; also on sheet 63
TA_PORZn: U10.4(A2) ; also on sheet 36 63
TA_POWERDOWNz: U10.3(A1) ; also on sheet 35 63
TA_RESETz: U10.5(A3) ; also on sheet 36 63
TA_SOC_INT1z: U10.6(A4) ; also on sheet 35 63
TA_SOC_INT2z: U10.7(A5) ; also on sheet 35 63
TM4C129_RST#: R735.2 TP3.1(TP)
TM4C129_TCK: TP12.1(TP) U170.100(PC0/TCK/SWCLK)
TM4C129_TDI: TP8.1(TP) U170.98(PC2/TDI)
TM4C129_TDO: TP7.1(TP) U170.97(PC3/TDO/SWO)
TM4C129_TMS: TP11.1(TP) U170.99(PC1/TMS/SWDIO)
UART6_RXD: R602.1 ; also on sheet 19
UART6_TXD: R603.1 ; also on sheet 19
UART9_RXD: R604.1 ; also on sheet 19
UART9_TXD: R605.1 ; also on sheet 19
VSYS_3V3: C43.1 R1303.2 U10.1(VCCA) ; also on sheet 22 23 35 36 40 49 62 63 65 66 67 68 69 73 75 76 77 78 79
VSYS_IO_3V3: R596.2 R598.2 R1195.2 ; also on sheet 18 20 22 24 29 30 31 32 33 35 36 37 38 40 41 42 43 45 48 50 51 53 56 57 58 59 60 61 65 66 68 75 81 82
XDS110_BUF_SELn: U10.22(~{OE}) U29.1(~{1OE}) U29.4(~{2OE}) U29.10(~{3OE}) U29.13(~{4OE}) ; also on sheet 35
XDS110_EMU0: R789.1 U170.42(PF0) ; also on sheet 22
XDS110_EMU1: R784.1 U170.43(PF1) ; also on sheet 22
XDS110_PROG_STAZ1: R7.2 U170.4(PD3/AIN12)
XDS110_PROG_STAZ2: R5.1 U170.3(PD2/AIN13)
XDS110_TCK: U170.35(PA2/SSI0CLK) ; also on sheet 22
XDS110_TDI: U170.38(PA5/SSI0XDAT1) ; also on sheet 22
XDS110_TDO: U170.37(PA4/SSI0XDAT0) ; also on sheet 22
XDS110_TMS: U170.36(PA3/SSI0FSS) ; also on sheet 22
XDS110_TRST#: U170.40(PA6) ; also on sheet 22
XDS110_VBUS_DET: R69.2 R70.1 U170.1(PD0/AIN15)
XDS_PM1_SCL: R738.2 U29.8(3B) U170.82(PL1)
XDS_PM1_SDA: R742.2 U29.11(4B) U170.81(PL0)
XDS_PM2_SCL: R140.2 U29.3(1B) U170.49(PG0)
XDS_PM2_SDA: R139.2 U29.6(2B) U170.50(PG1)
XDS_RBIAS: R22.1 U170.59(RBAIS)
XDS_RESET#: R735.1 R736.2 R741.1 U170.70(~{RST})
XDS_SHIELD: J1.SH1 J1.SH2 J1.SH3 J1.SH4 J1.SH5 J1.SH6 L1.1
XDS_TA_BM_IOEXP_RSTn: U10.15(B7) U170.71(PM7)
XDS_TA_BOOTMODE_CNTL#: U10.16(B6) U170.72(PM6)
XDS_TA_PORZn: U10.20(B2) U170.77(PM1)
XDS_TA_POWERDOWNz: U10.21(B1) U170.78(PM0)
XDS_TA_RESETz: U10.19(B3) U170.76(PM2)
XDS_TA_SOC_INT1z: U10.18(B4) U170.74(PM4)
XDS_TA_SOC_INT2z: U10.17(B5) U170.73(PM5)
XDS_USB_D_N: J1.2(D-) U2.2(IO2) U170.93(PL7/USB0DM)
XDS_USB_D_P: J1.3(D+) U2.1(IO1) U170.94(PL6/USB0DP)
XDS_USB_ID: J1.4(ID) R750.2 U2.4(IO3)
XDS_VREF: C50.1 C54.1 R52.2 U13.3(CATHODE) U170.9(VREFA+)
N23200398: C552.1 R749.1 U170.96(PB1/USB0VBUS)
N23200403: R750.1 U170.95(PB0/USB0ID)
N23200423: R768.1 R770.2 U170.60(PK7)
N23200491: LD1.2(ANODE) R5.2
N23200507: R756.2 R761.1 U170.63(PK4)
N23200509: R15.2 R19.1 U170.61(PK6)
N23200516: R762.2 R767.1 U170.62(PK5)
N23200616: LD6.2(ANODE) R7.1
N33442693: R1186.2 SW13.1
N33442697: D42.1(K) R1186.1
N33442815: D43.1(K) R1188.1
N33442839: R1188.2 SW13.2
N37858028: R49.1 U10.2(DIR)
N37858624: C115.2 R1303.1 R1304.1 U29.14(VCC)
N37948258: TP5.1(TP) U170.75(PM3)

Not connected (* = marked no-connect by the designer): U2 5(IO4); U6 7(NC)*; U13 2(NC1)* 4(NC2)* 5(NC3)*; U109 6(NC1) 11(NC2) 12(NC3) 14(NC4); U170 2(PD1/AIN14)* 5(PQ0)* 6(PQ1)* 11(PQ2)* 12(PE3/AIN0)* 13(PE2/AIN1)* 14(PE1/AIN2)* 15(PE0/AIN3)* 18(PK0/AIN16)* 19(PK1/AIN17)* 20(PK2/AIN18)* 21(PK3/AIN19)* 22(PC7/C0-)* 23(PC6/C0+)* 24(PC5/C1+)* 25(PC4/C1-)* 27(PQ3)* 29(PH0)* 30(PH1)* 31(PH2)* 32(PH3)* 33(PA0/U0RX)* 34(PA1/U0TX)* 41(PA7)* 44(PF2)* 45(PF3)* 46(PF4)* 53(EN0RXIN)* 54(EN0RXIP)* 56(EN0RX0N)* 57(EN0RX0P)* 65(~{HIB})* 67(XOSC1)* 83(PL2)* 84(PL3)* 85(PL4)* 86(PL5)* 91(PB2/I2C0SCL)* 92(PB3/I2C0SDA)* 102(PQ4)* 103(PP2)* 104(PP3)* 105(PP4)* 106(PP5)* 107(PN0)* 108(PN1)* 109(PN2)* 110(PN3)* 111(PN4)* 112(PN5)* 116(PJ0)* 117(PJ1)* 118(PP0/C2+)* 119(PP1/C2-)* 120(PB5/AIN11)* 121(PB4/AIN10)* 123(PE4/AIN9)* 124(PE5/AIN8)* 125(PD4/AIN7)* 126(PD5/AIN6)* 127(PD6/AIN5)* 128(PD7/AIN4)*

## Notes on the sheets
sheet 46
- LIN INTERFACE
- (VBAT_LIN: 4V to 45V)
- Silkscreen: "LIN"
- LIN MASTER MODE
- Switch - CLOSE
- LIN SLAVE MODE
- Switch - OPEN
sheet 47
- XDS110 DEBUGGER
- 90E
- Silkscreen "XDS110"
- GREEN
- RED
- SN74AVC8T245PWR buffer is used to isolate test
  automation from xds110
- Set the unique ID
  of the debugger
